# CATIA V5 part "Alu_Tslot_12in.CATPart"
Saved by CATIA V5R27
Part number: Tslotted_12in
Revision: ANY
Definition: UNKNOWN
Nomenclature: Tslotted_12in
Source: Unknown
Bounding box of the stored display mesh (mm): x -19.056 to 19.056, y -19.056 to 19.056, z -1524 to -1216.66
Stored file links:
  \\triton.meca.polymtl.ca\usagers\zaoue\profiles\Desktop\varm_ass\bearing assy\Alu_Tslot_12in.CATPart
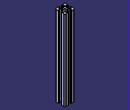
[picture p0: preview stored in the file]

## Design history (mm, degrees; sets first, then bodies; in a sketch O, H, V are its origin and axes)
Body1 "Boss-Extrude1" (main body)
  Solid1: solid without history
  Sketch1 on face of Solid1, origin (0, 0, 1524), H (1, 0, 0), V (0, 1, 0)
    line L1 (-31.855, 32.792) -> (28.107, 32.792)
    line L2 (28.107, 32.792) -> (28.107, -28.509)
    line L3 (28.107, -28.509) -> (-31.855, -28.509)
    line L4 (-31.855, -28.509) -> (-31.855, 32.792)
    horizontal: L1 H, L3 H
    vertical: L2 V, L4 V
    fix: L1, L2, L3, L4
  Pocket1: profile Sketch1, direction (0, 0, -1), length 2740.66
  Sketch2 on face of Solid1, origin (0, 0, -1524), H (1, 0, 0), V (0, -1, 0)
    line L1 (19.0564, -14.3256) -> (19.0564, -15.8623)
    arc A1 centre (19.0564, -15.0939) radius 0.7684 from (19.0564, -14.3256) to (19.0564, -15.8623) ccw
    point P3 (19.0564, -15.0939)
    line L2 (7.9756, -19.05) -> (9.4996, -19.05)
    arc A2 centre (8.7376, -19.05) radius 0.762 from (9.4996, -19.05) to (7.9756, -19.05) ccw
    point P6 (8.7376, -19.05)
    line L3 (19.05, -7.9756) -> (19.05, -9.4996)
    point P7 (19.05, -8.7376)
    arc A3 centre (19.05, -8.7376) radius 0.762 from (19.05, -7.9756) to (19.05, -9.4996) ccw
    line L4 (19.05, 9.4996) -> (19.05, 7.9756)
    point P10 (19.05, 8.7376)
    arc A4 centre (19.05, 8.7376) radius 0.762 from (19.05, 9.4996) to (19.05, 7.9756) ccw
    line L5 (19.0564, 15.8623) -> (19.0564, 14.3256)
    point P13 (19.0564, 15.0939)
    arc A5 centre (19.0564, 15.0939) radius 0.7684 from (19.0564, 15.8623) to (19.0564, 14.3256) ccw
    line L6 (-9.4996, -19.05) -> (-7.9756, -19.05)
    point P16 (-8.7376, -19.05)
    arc A6 centre (-8.7376, -19.05) radius 0.762 from (-7.9756, -19.05) to (-9.4996, -19.05) ccw
    line L7 (-15.8623, -19.0563) -> (-14.3256, -19.0563)
    point P19 (-15.0939, -19.0563)
    arc A7 centre (-15.0939, -19.0563) radius 0.7684 from (-14.3256, -19.0563) to (-15.8623, -19.0563) ccw
    line L8 (14.3256, -19.0563) -> (15.8623, -19.0563)
    point P22 (15.0939, -19.0563)
    arc A8 centre (15.0939, -19.0563) radius 0.7684 from (15.8623, -19.0563) to (14.3256, -19.0563) ccw
    reference projected arc E1 centre (19.0564, -15.0939) radius 0.7684 from (19.05, -14.3256) to (18.288, -15.0939) ccw from edge [face of Solid1 | face of Solid1]
    reference projected arc E2 centre (19.0564, -15.0939) radius 0.7684 from (19.05, -14.3256) to (18.288, -15.0939) ccw from edge [face of Solid1 | face of Solid1]
    reference projected arc E3 centre (19.05, 8.7376) radius 0.762 from (19.05, 9.4996) to (18.288, 8.7376) ccw from edge [face of Solid1 | face of Solid1]
    reference projected arc E4 centre (19.05, 8.7376) radius 0.762 from (19.05, 9.4996) to (18.288, 8.7376) ccw from edge [face of Solid1 | face of Solid1]
    reference projected arc E5 centre (19.0564, 15.0939) radius 0.7684 from (19.05, 15.8623) to (18.288, 15.0939) ccw from edge [face of Solid1 | face of Solid1]
    reference projected arc E6 centre (19.0564, 15.0939) radius 0.7684 from (19.05, 15.8623) to (18.288, 15.0939) ccw from edge [face of Solid1 | face of Solid1]
    reference projected arc E7 centre (19.05, -8.7376) radius 0.762 from (19.05, -7.9756) to (18.288, -8.7376) ccw from edge [face of Solid1 | face of Solid1]
    reference projected arc E8 centre (19.05, -8.7376) radius 0.762 from (19.05, -7.9756) to (18.288, -8.7376) ccw from edge [face of Solid1 | face of Solid1]
    reference projected arc E9 centre (15.0939, -19.0563) radius 0.7684 from (15.8623, -19.05) to (14.3256, -19.05) ccw from edge [face of Solid1 | face of Solid1]
    reference projected arc E10 centre (15.0939, -19.0563) radius 0.7684 from (15.8623, -19.05) to (14.3256, -19.05) ccw from edge [face of Solid1 | face of Solid1]
    reference projected arc E11 centre (8.7376, -19.05) radius 0.762 from (9.4996, -19.05) to (7.9756, -19.05) ccw from edge [face of Solid1 | face of Solid1]
    reference projected arc E12 centre (8.7376, -19.05) radius 0.762 from (9.4996, -19.05) to (7.9756, -19.05) ccw from edge [face of Solid1 | face of Solid1]
    reference projected arc E13 centre (-8.7376, -19.05) radius 0.762 from (-7.9756, -19.05) to (-9.4996, -19.05) ccw from edge [face of Solid1 | face of Solid1]
    reference projected arc E14 centre (-8.7376, -19.05) radius 0.762 from (-7.9756, -19.05) to (-9.4996, -19.05) ccw from edge [face of Solid1 | face of Solid1]
    reference projected arc E15 centre (-15.0939, -19.0563) radius 0.7684 from (-14.3256, -19.05) to (-15.8623, -19.05) ccw from edge [face of Solid1 | face of Solid1]
    reference projected arc E16 centre (-15.0939, -19.0563) radius 0.7684 from (-14.3256, -19.05) to (-15.8623, -19.05) ccw from edge [face of Solid1 | face of Solid1]
    vertical: L1 V, L3 V, L4 V, L5 V
    midpoint: P3 L1, P6 L2, P7 L3, P10 L4, P13 L5, P16 L6, P19 L7, P22 L8
    horizontal: L2 H, L6 H, L7 H, L8 H
    coincidence: A1 E1, A4 E3, A5 E5, A3 E7, A8 E9, A2 E11, A6 E13, A7 E15
    concentricity: A1 E2, A4 E4, A5 E6, A3 E8, A8 E10, A2 E12, A6 E14, A7 E16
  Pad1: profile Sketch2, direction (0, 0, -1), up to end face of Pocket1
  Mirror1: of Pad1, about {plane type Offset, RefPlane face of Solid1, Offset 19.05}
  Mirror2: of Pad1, about {plane type Offset, RefPlane face of Solid1, Offset 19.05}
  Plane1: type Offset, RefPlane face of Solid1, Offset 153.67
